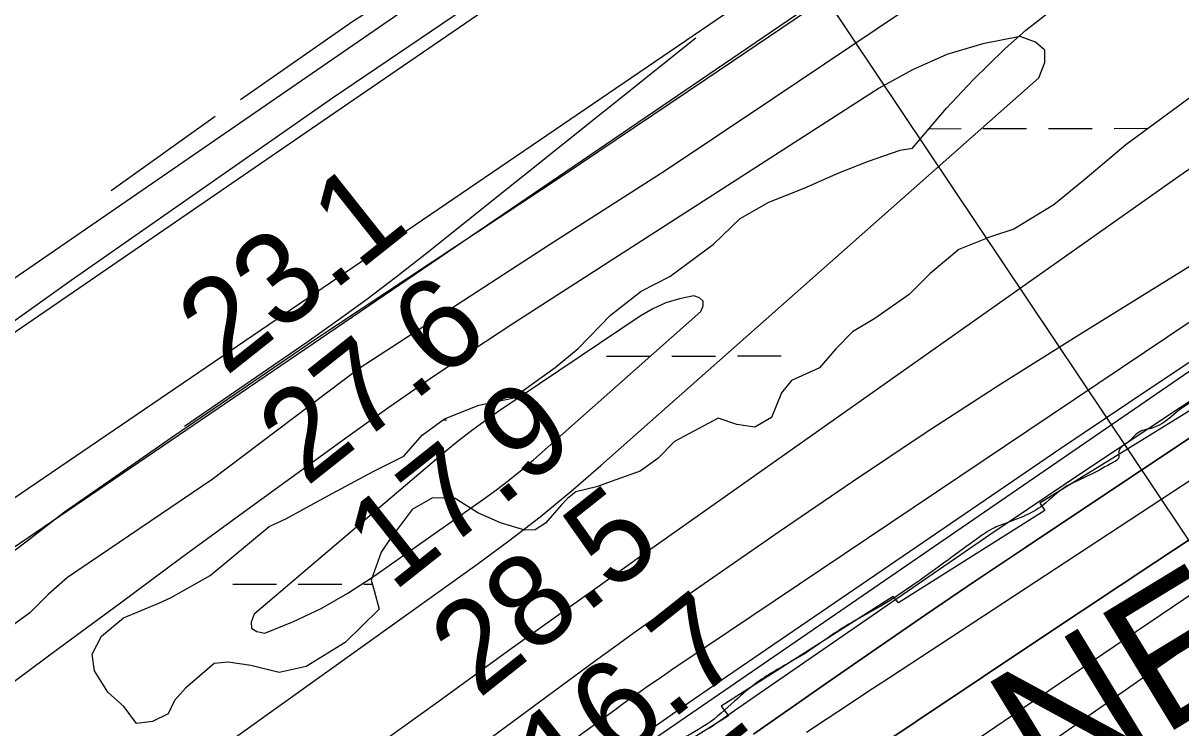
# Model space of a CAD drawing. Extents: x 3324104 to 3361979, y 612876 to 638273.
# Drawn here: x 3352974 to 3353821, y 621446 to 621962 of the extents above; entities that cross this region are included whole.
import ezdxf

# ---------------------------------------------------------------- set-up
doc = ezdxf.new("R2010")
doc.units = 0
for name, color, linetype in [('V-FLOD-BASE', 7, 'Continuous'), ('V-LEVE-TOET', 7, 'Continuous'), ('V-RIVR-EDGE', 7, 'Continuous'), ('V-RIVR-RANG', 7, 'Continuous'), ('V-ROAD-CNTR', 7, 'Continuous'), ('V-RRAP-FSHR', 7, 'Continuous'), ('V-RRAP-RVMT', 7, 'Continuous'), ('V-RRAP-RVMT-IDEN', 7, 'Continuous'), ('V-SURV-LINE', 7, 'Continuous'), ('V-TOPO-DPTH', 7, 'Continuous'), ('V-TOPO-MAJR', 7, 'Continuous'), ('V-TOPO-MINR', 7, 'Continuous'), ('V-TOPO-SHOR', 7, 'Continuous'), ('V-TOPO-WATR', 7, 'Continuous'), ('V-WETL-SWMP', 7, 'Continuous')]:
    doc.layers.add(name, color=color, linetype=linetype)

msp = doc.modelspace()

# ---------------------------------------------------------------- linework, layer by layer
at = {"layer": 'V-FLOD-BASE'}
msp.add_lwpolyline([(3352733.39, 621421.22), (3352808.07, 621469.05), (3352880.67, 621518.91), (3352907.8, 621537.87), (3352926.16, 621547.76), (3352952.63, 621565.33), (3352977.71, 621584.25), (3353004.14, 621604.57), (3353084.86, 621660.73), (3353186.64, 621730.26), (3353290.48, 621799.14), (3353369.22, 621851.16), (3353473.73, 621921.42), (3353593.83, 622002.91), (3353711.85, 622086.42), (3353832.66, 622166.54)], dxfattribs=at)
at = {"layer": 'V-LEVE-TOET'}
for points in [[(3352048.33, 621149.58), (3352281.39, 621294.26), (3352547.43, 621455.43), (3352729.05, 621574.03), (3352943.48, 621719.74), (3353193.4, 621891.29), (3353438.06, 622058.76), (3353677.49, 622220.84), (3353834.04, 622327.06), (3353864.34, 622344.83), (3353996.2, 622414.76), (3354263.85, 622558.67), (3354497.32, 622678.09), (3354750.45, 622815.11), (3355094.52, 623002.8), (3355436.28, 623169.16), (3355691.22, 623286.64)], [(3353844.21, 622130.37), (3353724.14, 622046.83), (3353616.99, 621970.35), (3353522.66, 621907.11), (3353443.93, 621854.41), (3353359.06, 621800.24), (3353219.89, 621709.53), (3353112.14, 621628.24), (3353006.28, 621556.59), (3352992.07, 621544.02)], [(3352992.07, 621544.02), (3352978.57, 621530.77), (3352962.29, 621518.84), (3352945.95, 621511.72), (3352931.66, 621504.64), (3352890.23, 621478.6), (3352825.74, 621436.41), (3352742.94, 621381.59), (3352604.42, 621293.63), (3352521.58, 621240.87), (3352486.39, 621210.81), (3352457.38, 621180.85), (3352433.13, 621153.03), (3352416.22, 621137.67), (3352403.32, 621129.92), (3352389.05, 621121.45), (3352371.31, 621115.69), (3352326.17, 621107.42), (3352304.33, 621100.21), (3352274.37, 621086.7), (3352237.68, 621064.85)]]:
    msp.add_lwpolyline(points, dxfattribs=at)
at = {"layer": 'V-RIVR-EDGE'}
msp.add_spline([(3356051.95, 622889.63), (3356029.15, 622881.43), (3356012.46, 622875.66), (3355994.6, 622867.17), (3355977.52, 622859.07), (3355958.5, 622850.97), (3355948.4, 622843.24), (3355934.03, 622834.75), (3355904.12, 622817.76), (3355878.1, 622802.31), (3355856.74, 622790.34), (3355829.95, 622776.44), (3355805.11, 622765.65), (3355764.72, 622744.81), (3355744.14, 622733.61), (3355694.06, 622710.85), (3355668.43, 622698.12), (3355641.64, 622685), (3355605.15, 622669.19), (3355569.44, 622657.26), (3355539.17, 622646.47), (3355510.83, 622636.85), (3355482.11, 622628.39), (3355461.93, 622623.01), (3355442.52, 622614.14), (3355422.73, 622607.21), (3355409.53, 622603.36), (3355388.97, 622597.59), (3355371.88, 622589.49), (3355348.98, 622581.02), (3355297.71, 622547.02), (3355260.04, 622525.78), (3355211.1, 622494.49), (3355190.13, 622484.46), (3355184.7, 622482.92), (3355179.26, 622477.89), (3355174.21, 622475.58), (3355160.62, 622470.96), (3355143.54, 622463.63), (3355133.06, 622457.07), (3355125.67, 622450.49), (3355113.25, 622443.93), (3355096.93, 622433.11), (3355081.02, 622426.95), (3355064.32, 622419.23), (3355056.95, 622418.86), (3355048.8, 622414.62), (3355041.8, 622406.88), (3355036.76, 622406.5), (3355031.32, 622405.74), (3355027.05, 622404.2), (3355017.34, 622396.08), (3355010.74, 622394.93), (3355001.42, 622388.36), (3354988.6, 622379.09), (3354972.29, 622369.43), (3354947.44, 622356.31), (3354937.73, 622351.68), (3354926.08, 622343.56), (3354903.15, 622326.56), (3354891.11, 622318.06), (3354883.33, 622307.22), (3354879.44, 622304.12), (3354875.17, 622302.58), (3354867.8, 622299.11), (3354853.03, 622288.29), (3354842.54, 622279.01), (3354826.61, 622267.41), (3354807.2, 622259.71), (3354793.23, 622255.47), (3354765.68, 622249.73), (3354748.61, 622245.5), (3354734.63, 622239.33), (3354712.11, 622227.37), (3354697.74, 622218.87), (3354685.31, 622209.98), (3354640.65, 622184.5), (3354622.01, 622176.01), (3354616.19, 622175.25), (3354603.38, 622167.52), (3354578.92, 622157.11), (3354554.46, 622147.48), (3354537.39, 622142.87), (3354530.78, 622137.84), (3354500.11, 622122.79), (3354463.61, 622102.33), (3354417.79, 622078.79), (3354386.33, 622060.64), (3354340.11, 622032.44), (3354321.08, 622021.25), (3354284.96, 621998.84), (3354257, 621982.24), (3354217, 621958.68), (3354194.08, 621942.84), (3354176.99, 621931.63), (3354157.57, 621921.98), (3354141.64, 621910.39), (3354135.42, 621904.2), (3354130.36, 621897.62), (3354120.65, 621891.05), (3354103.96, 621882.95), (3354075.58, 621856.65), (3354044.89, 621835.39), (3354013.04, 621812.21), (3353971.47, 621781.67), (3353947.77, 621763.5), (3353941.17, 621763.52), (3353935.35, 621762.76), (3353929.53, 621760.06), (3353924.87, 621756.58), (3353920.59, 621751.55), (3353917.08, 621742.64), (3353910.48, 621741.49), (3353904.66, 621738.4), (3353893.78, 621731.06), (3353879.8, 621721.4), (3353866.19, 621708.64), (3353854.92, 621697.42), (3353843.26, 621687.75), (3353839.77, 621688.54), (3353831.23, 621686.23), (3353823.08, 621681.21), (3353818.03, 621677.34), (3353800.94, 621666.14), (3353790.85, 621663.06), (3353781.91, 621654.94), (3353777.63, 621651.85), (3353776.07, 621648.75), (3353775.67, 621643.71), (3353772.18, 621641), (3353755.87, 621632.13), (3353735.68, 621622.09), (3353718.58, 621608.17), (3353704.21, 621600.45), (3353694.12, 621596.6), (3353683.64, 621592.36), (3353671.21, 621584.25), (3353642.07, 621562.99), (3353598.95, 621534.01), (3353578.37, 621522.43), (3353556.23, 621507.75), (3353547.68, 621501.95), (3353525.93, 621489.21), (3353513.12, 621481.09), (3353497.18, 621468.34), (3353476.98, 621450.94), (3353453.28, 621436.65), (3353435.8, 621424.67), (3353404.72, 621401.09), (3353378.3, 621380.21), (3353361.59, 621368.62), (3353339.46, 621355.1), (3353319.65, 621342.35), (3353299.45, 621329.99), (3353283.54, 621324.6), (3353273.05, 621317.65), (3353254.77, 621295.98), (3353236.88, 621275.47), (3353219.39, 621258.83), (3353195.69, 621241.44), (3353168.49, 621221.34), (3353137.81, 621201.64), (3353112.17, 621185.03), (3353065.55, 621151.79), (3353022.05, 621122.82), (3352993.29, 621100.39), (3352956, 621073.34), (3352907.05, 621037.78), (3352853.8, 620991.77), (3352787.76, 620942.29), (3352749.68, 620913.3), (3352736.85, 620900.92), (3352733.34, 620892.79), (3352728.67, 620886.59), (3352718.96, 620881.19), (3352691.78, 620864.58), (3352660.31, 620841.78), (3352640.5, 620828.25), (3352623.39, 620811.23), (3352605.12, 620792.27), (3352593.46, 620783), (3352582.59, 620778.76), (3352566.29, 620771.43), (3352548.04, 620764.49), (3352522.41, 620750.98), (3352494.45, 620735.54), (3352482.41, 620727.04), (3352479.3, 620723.17), (3352476.96, 620717.36), (3352470.74, 620711.94), (3352455.99, 620707.33), (3352443.18, 620700.38), (3352419.1, 620685.7), (3352392.3, 620669.09), (3352362.78, 620650.94), (3352339.08, 620634.32), (3352315.38, 620615.38), (3352284.68, 620590.63), (3352258.65, 620571.31), (3352228.74, 620550.05), (3352193.39, 620527.65), (3352156.88, 620504.86), (3352131.63, 620487.47), (3352093.95, 620462.36), (3352049.28, 620432.99), (3351990.23, 620391.26), (3351936.63, 620357.26), (3351851.55, 620293.87), (3351833.29, 620281.51), (3351816.98, 620273.79), (3351794.06, 620257.95), (3351767.65, 620240.95), (3351719.86, 620206.17), (3351680.63, 620177.57), (3351657.32, 620160.56), (3351637.11, 620145.87), (3351623.13, 620135.44), (3351603.32, 620124.24), (3351588.57, 620120.01), (3351567.22, 620109.59), (3351552.08, 620103.43), (3351538.1, 620096.48), (3351523.73, 620086.43), (3351510.91, 620076.38), (3351503.52, 620069.81), (3351495.35, 620057.42), (3351486, 620042.32), (3351479.39, 620032.64), (3351469.67, 620022.58), (3351448.3, 620006.34), (3351431.59, 619994.75), (3351404.78, 619973.88), (3351377.97, 619951.84), (3351358.93, 619936.37), (3351332.12, 619915.5), (3351306.08, 619892.29), (3351274.58, 619858.25), (3351238.83, 619826.92), (3351215.12, 619805.65), (3351171.59, 619767.75), (3351145.54, 619739.51), (3351124.55, 619722.11), (3351105.9, 619707.81), (3351089.59, 619696.99), (3351079.49, 619691.2), (3351074.04, 619683.45), (3351058.1, 619666.43), (3351043.34, 619655.22), (3351015.36, 619633.96), (3350999.05, 619623.14), (3350992.05, 619617.34), (3350979.23, 619606.13), (3350966.01, 619594.53), (3350951.25, 619582.15), (3350935.7, 619567.84), (3350923.26, 619555.08), (3350910.05, 619544.25), (3350888.29, 619528.02), (3350846.74, 619504.08), (3350821.49, 619490.18), (3350811.39, 619483.61), (3350805.96, 619480.52), (3350800.9, 619473.16), (3350797.41, 619473.17), (3350793.92, 619474.35), (3350788.88, 619473.58), (3350786.93, 619472.04), (3350785.37, 619467.39), (3350785.36, 619462.73), (3350779.53, 619456.15), (3350765.93, 619445.72), (3350746.11, 619428.7), (3350722.4, 619408.98), (3350716.19, 619407.06), (3350713.08, 619403.96), (3350711.13, 619396.99), (3350708.79, 619391.57), (3350704.52, 619391.58), (3350693.26, 619385.79), (3350686.65, 619379.6), (3350679.64, 619368.37), (3350661.38, 619354.45), (3350648.56, 619344.4), (3350645.46, 619344.8), (3350638.47, 619339.39), (3350623.32, 619330.5), (3350616.33, 619326.26), (3350602.35, 619317.37), (3350598.83, 619308.85), (3350582.91, 619299.19), (3350553.77, 619276), (3350526.18, 619255.51), (3350493.55, 619231.94), (3350474.9, 619219.57), (3350474.5, 619213.76), (3350470.22, 619207.17), (3350458.96, 619202.55), (3350446.14, 619194.05), (3350441.09, 619189.79), (3350438.76, 619186.31), (3350434.48, 619180.89), (3350414.67, 619167.76), (3350401.46, 619159.26), (3350384.75, 619146.89), (3350369.6, 619133.74), (3350356.39, 619125.24), (3350350.95, 619119.05), (3350347.43, 619109.36), (3350338.1, 619097.75), (3350324.88, 619083.82), (3350308.55, 619069.9), (3350300.39, 619062.56), (3350296.13, 619062.57), (3350291.47, 619062.19), (3350274.77, 619050.6), (3350258.45, 619037.45), (3350251.84, 619032.81), (3350244.08, 619029.34), (3350233.61, 619028.21), (3350227.39, 619024.34), (3350220.39, 619016.99), (3350213, 619007.32), (3350202.12, 618996.87), (3350193.57, 618989.52), (3350179.6, 618985.29), (3350173.77, 618980.65), (3350164.84, 618977.96), (3350162.12, 618975.25), (3350159.39, 618971.38), (3350154.33, 618963.64), (3350145.78, 618953.19), (3350125.96, 618938.11), (3350102.66, 618923.05), (3350094.5, 618918.41), (3350086.34, 618913), (3350075.07, 618901.01), (3350064.19, 618892.12), (3350039.32, 618873.57), (3350021.84, 618861.59), (3350002.03, 618848.84), (3349991.94, 618844.21), (3349964.36, 618826.44), (3349938.72, 618807.11), (3349915.41, 618792.82), (3349892.5, 618778.92), (3349868.02, 618761.91), (3349852.49, 618753.03), (3349842.79, 618749.95), (3349830.35, 618739.13), (3349804.32, 618720.19), (3349777.9, 618697.76), (3349751.86, 618677.66), (3349729.72, 618661.43), (3349703.69, 618642.88), (3349678.84, 618629.75), (3349648.93, 618611.99), (3349624.46, 618594.99), (3349592.61, 618575.67), (3349570.48, 618564.87), (3349549.5, 618548.63), (3349505.21, 618518.11), (3349479.19, 618499.94), (3349471.42, 618494.53), (3349458.99, 618487.59), (3349438.4, 618472.12), (3349412.37, 618452.41), (3349379.73, 618429.61), (3349350.21, 618410.29), (3349303.2, 618374.73), (3349277.56, 618357.73), (3349263.97, 618347.29), (3349241.43, 618330.68), (3349226.67, 618319.85), (3349207.25, 618306.33), (3349193.17, 618293.54)], degree=3, dxfattribs=at)
at = {"layer": 'V-RIVR-RANG'}
msp.add_line((3353550.98, 621996.45), (3354073.67, 621215.16), dxfattribs=at)
at = {"layer": 'V-ROAD-CNTR'}
msp.add_lwpolyline([(3353867.53, 622388.29), (3353812.96, 622356.52), (3353775.17, 622330.65), (3353711.04, 622287.55), (3353347.4, 622037.39), (3352894.69, 621725.66), (3352781.25, 621646.98), (3352684.03, 621579.35), (3352627.31, 621541.21), (3352581, 621513.51), (3352520.9, 621474.1), (3352415.36, 621410.23), (3351812.2, 621048.45), (3351739.17, 621002.97), (3351683.58, 620968.21)], dxfattribs=at)
at = {"layer": 'V-RRAP-FSHR'}
msp.add_lwpolyline([(3349156.55, 618293.48), (3349290.84, 618378.98), (3349409.37, 618477.79), (3349541.25, 618565.26), (3349771.64, 618715.9), (3349922.45, 618808.45), (3350215.79, 619019.76), (3350269.12, 619069.35), (3350501.35, 619248.31), (3350630.24, 619348.58), (3350981.59, 619636.83), (3351335.34, 619937.32), (3351550.69, 620108.65), (3351713.66, 620224.46), (3351812.36, 620304.63), (3352053.37, 620458.3), (3352414.71, 620728.03), (3352590.48, 620825.76), (3352682.34, 620894.14), (3352964.07, 621108.39), (3353211.76, 621284.79), (3354078.79, 621880.27)], dxfattribs=at)
at = {"layer": 'V-RRAP-RVMT'}
for p, q in [((3353833.32, 621682.07), (3353718.1, 621610.97)), ((3353718.1, 621610.97), (3353721.76, 621605.59)), ((3353721.76, 621605.59), (3353614.57, 621538.04)), ((3353610.69, 621542.69), (3353484.75, 621462.36)), ((3353614.57, 621538.04), (3353610.69, 621542.69)), ((3353484.75, 621462.36), (3353490.2, 621455.25)), ((3353490.2, 621455.25), (3353362.21, 621375.5))]:
    msp.add_line(p, q, dxfattribs=at)
at = {"layer": 'V-SURV-LINE'}
for points in [[(3352745.54, 621464.15), (3353945.71, 622281.36)], [(3353962.59, 622256.56), (3352762.42, 621439.34)]]:
    msp.add_lwpolyline(points, dxfattribs=at)
at = {"layer": 'V-TOPO-DPTH'}
for points in [[(3353508.48, 621441.86), (3353562.01, 621479.23), (3353598.23, 621504.35), (3353634.56, 621529.31), (3353671.04, 621554.03), (3353707.63, 621578.6), (3354161.88, 621881.5)], [(3353508.48, 621441.86), (3353562.01, 621479.23), (3353598.23, 621504.35), (3353634.56, 621529.31), (3353671.04, 621554.03), (3353707.63, 621578.6), (3354161.88, 621881.5)], [(3353868.06, 621740.85), (3353800.28, 621695.89), (3353732.83, 621650.44), (3353518.02, 621503.97), (3353489.5, 621484.39), (3353461.05, 621464.7), (3353432.72, 621444.85)], [(3354109.79, 621703.92), (3353576.52, 621331.22)], [(3354109.79, 621703.92), (3353576.52, 621331.22)], [(3353579.77, 621419.09), (3353724.04, 621515.5), (3353803.01, 621568.04), (3353882.11, 621620.39)], [(3353882.11, 621620.39), (3353803.01, 621568.04), (3353724.04, 621515.5), (3353579.77, 621419.09)]]:
    msp.add_lwpolyline(points, dxfattribs=at)
at = {"layer": 'V-TOPO-MAJR'}
for points in [[(3353077.77, 621402.88), (3353305.91, 621566.06), (3353329.3, 621583.35), (3353352.31, 621601.11), (3353374.77, 621619.59), (3353396.84, 621638.53), (3353717.48, 621922.52), (3353721.85, 621933.59), (3353721.76, 621942.64), (3353715, 621948.65), (3353703.79, 621952.64), (3353676.52, 621947.24), (3353650.09, 621939.54), (3353624.91, 621928.39), (3353600.58, 621914.95), (3353332.95, 621742.72), (3353302.21, 621722.57), (3353271.71, 621702.09), (3353241.55, 621681.09), (3353211.63, 621659.75), (3353180.48, 621637.14), (3353135.21, 621604.17), (3353090.02, 621571.1), (3353044.93, 621537.88), (3352999.91, 621504.57), (3352735.46, 621308.17)], [(3353091.79, 621667.31), (3353181.43, 621728.93), (3353203.53, 621744.48), (3353225.4, 621760.34), (3353246.92, 621776.68), (3353268.21, 621793.32), (3353466.35, 621951.78)], [(3353861.45, 621879.01), (3353819.82, 621850.09), (3353456.56, 621593.69), (3353425.13, 621571.44), (3353393.75, 621549.13), (3353362.44, 621526.72), (3353331.17, 621504.25), (3353316.06, 621493.35), (3353277.27, 621465.4), (3353238.46, 621437.46)]]:
    msp.add_lwpolyline(points, dxfattribs=at)
at = {"layer": 'V-TOPO-MINR'}
for points in [[(3354043.85, 621918.19), (3353744.67, 621732.73), (3353689.66, 621698.03), (3353635.02, 621662.76), (3353580.94, 621626.65), (3353527.23, 621589.97), (3353448.41, 621535.24), (3353434.43, 621525.45), (3353420.51, 621515.57), (3353406.67, 621505.58), (3353392.88, 621495.5), (3352987.58, 621196.59)], [(3353912.95, 621800.7), (3353456.83, 621494.35), (3353450.53, 621490.09), (3353444.24, 621485.81), (3353437.98, 621481.49), (3353431.73, 621477.16), (3353425.51, 621472.79), (3353419.29, 621468.4), (3353413.1, 621463.98), (3353406.93, 621459.54), (3352864.43, 621067.84)], [(3354206.15, 621799.15), (3353788.86, 621517.01), (3353748.88, 621489.94), (3353708.92, 621462.83), (3353669, 621435.67)], [(3353302.09, 621664.08), (3353292.46, 621656.52), (3353282.99, 621648.75), (3353142.81, 621529.7), (3353140.77, 621523.89), (3353141.04, 621519.43), (3353144.79, 621516.98), (3353150.84, 621515.88), (3353171.66, 621524.4), (3353191.93, 621533.97), (3353211.38, 621545.12), (3353230.28, 621557.33), (3353312.64, 621615.27), (3353321.61, 621621.81), (3353330.44, 621628.55), (3353339.03, 621635.58), (3353347.47, 621642.81), (3353469.94, 621751.28), (3353471.61, 621755.51), (3353471.58, 621758.96), (3353469, 621761.26), (3353464.71, 621762.79), (3353454.32, 621760.69), (3353444.27, 621757.69), (3353434.73, 621753.31), (3353425.54, 621748.02), (3353322.01, 621678.31), (3353311.97, 621671.3), (3353302.09, 621664.08)], [(3353868.06, 621740.85), (3353800.28, 621695.89), (3353732.83, 621650.44), (3353518.02, 621503.97), (3353489.5, 621484.39), (3353461.05, 621464.7), (3353432.72, 621444.85)], [(3353891.14, 621726.73), (3353821.21, 621681.04), (3353751.56, 621634.93), (3353682.34, 621588.2), (3353613.39, 621541.04), (3353512.97, 621471.69), (3353494.48, 621458.83), (3353476.05, 621445.9)], [(3353976.3, 621724.76), (3353607.3, 621482.6), (3353592.32, 621472.74), (3353577.34, 621462.88), (3353562.38, 621452.99), (3353547.43, 621443.08)], [(3354109.79, 621703.92), (3353576.52, 621331.22)], [(3353882.11, 621620.39), (3353803.01, 621568.04), (3353724.04, 621515.5), (3353579.77, 621419.09)]]:
    msp.add_lwpolyline(points, dxfattribs=at)
at = {"layer": 'V-TOPO-SHOR'}
msp.add_line((3353114.34, 621894.19), (3353038.28, 621839.61), dxfattribs=at)
for points in [[(3355651.33, 623306.1), (3355443.74, 623204.7), (3355259.41, 623107.78), (3355126.02, 623041.86), (3354985.99, 622962.8), (3354786.02, 622856.72), (3354599.02, 622754.96), (3354402.53, 622646.19), (3354239.91, 622564.02), (3354045.44, 622458.03), (3353808.21, 622323.23), (3353722.68, 622266.99), (3353654.19, 622217.88), (3353559.9, 622151.89), (3353401.12, 622043.72), (3353200.27, 621907.45), (3353008.97, 621774.07), (3352819.08, 621638.65), (3352713.88, 621569.06), (3352571.34, 621474.87), (3352516.97, 621443.14), (3352461.97, 621408.65), (3352340.37, 621334.68), (3352239.82, 621274.09)], [(3353261.08, 621992.88), (3353215.11, 621963.72), (3353132.86, 621906.27)]]:
    msp.add_lwpolyline(points, dxfattribs=at)
at = {"layer": 'V-TOPO-WATR'}
msp.add_lwpolyline([(3354161.88, 621881.5), (3353707.63, 621578.6), (3353671.04, 621554.03), (3353634.56, 621529.31), (3353598.23, 621504.35), (3353562.01, 621479.23), (3353508.48, 621441.86)], dxfattribs=at)
at = {"layer": 'V-WETL-SWMP'}
for p, q in [((3353636.99, 621885.18), (3353660.5, 621885.23)), ((3353676.5, 621885.25), (3353708.5, 621885.31)), ((3353724.5, 621885.34), (3353756.5, 621885.39)), ((3353772.5, 621885.42), (3353797.52, 621885.46)), ((3353400.79, 621718.6), (3353432.79, 621718.65)), ((3353448.79, 621718.68), (3353480.79, 621718.74)), ((3353496.79, 621718.77), (3353528.79, 621718.82)), ((3353281.27, 621671.96), (3353283.81, 621671.96)), ((3353127.17, 621551.62), (3353159.17, 621551.67)), ((3353175.17, 621551.7), (3353207.17, 621551.76)), ((3353223.17, 621551.79), (3353229.41, 621551.8))]:
    msp.add_line(p, q, dxfattribs=at)
for points in [[(3353403.85, 621748.72), (3353426.2, 621766.22), (3353447.3, 621776.85), (3353479.15, 621800.68), (3353498.74, 621819.51), (3353519.81, 621831.51), (3353545.72, 621841.53), (3353570.92, 621852.91), (3353592.73, 621861.48), (3353615.92, 621869.4), (3353624.82, 621870.91), (3353649.73, 621900.12), (3353669.29, 621921.01), (3353692.25, 621943.33), (3353707.8, 621957.29), (3353726.77, 621972), (3353753.32, 621984.77), (3353777.8, 621998.2), (3353808.56, 622004.86), (3353833.84, 622010.75)], [(3353840.15, 621916.88), (3353781.17, 621873.41), (3353751.39, 621848.24), (3353728.37, 621829.36), (3353699.16, 621811.74), (3353682.1, 621805.98), (3353658.93, 621796.69), (3353637.94, 621779.21), (3353622.41, 621763.87), (3353597.31, 621746.32), (3353581.01, 621736.46), (3353568.86, 621723.92), (3353556.74, 621710.01), (3353536.31, 621700.76), (3353528.91, 621691.73), (3353521.65, 621673.78), (3353509.42, 621666.72), (3353496.35, 621668.57), (3353482.56, 621673.16), (3353450.6, 621656.18), (3353438.45, 621643.64), (3353425.56, 621634.52), (3353407.83, 621628.06), (3353393.51, 621623.03), (3353378.48, 621619.36), (3353372.38, 621614.46)], [(3353372.38, 621614.46), (3353367.66, 621609.59), (3353356.21, 621596.37), (3353348.74, 621591.45), (3353341.2, 621591.33), (3353323.28, 621596.53), (3353306.71, 621603.81), (3353290.07, 621614.52), (3353273.6, 621614.94), (3353258.65, 621606.47), (3353242.53, 621584.95), (3353235.83, 621575.24), (3353228.61, 621554.55), (3353230.79, 621547.04), (3353234.44, 621533.38), (3353209.45, 621508.97), (3353180.92, 621491.37), (3353161.1, 621486.94), (3353140.44, 621492.09), (3353123.94, 621494.57), (3353113.67, 621493.72), (3353092.69, 621475.55), (3353084.6, 621466.51), (3353079.96, 621456.83), (3353068.39, 621451.16), (3353056.75, 621449.6), (3353047.64, 621461.8), (3353035.81, 621472.59), (3353025.96, 621488.2), (3353024.39, 621500.53), (3353031.04, 621513.67), (3353047.29, 621526.96), (3353073.18, 621537.66), (3353082.03, 621541.92), (3353110.58, 621558.15), (3353153.91, 621593.82), (3353166.16, 621599.51), (3353196.76, 621616.46), (3353230.08, 621634.14), (3353252.54, 621645.47), (3353266.01, 621660.78), (3353282.28, 621672.7), (3353307.5, 621682.7), (3353332.11, 621687.9), (3353363.31, 621710.35), (3353380.23, 621724.33), (3353403.85, 621748.72)]]:
    msp.add_lwpolyline(points, dxfattribs=at)

# ---------------------------------------------------------------- texts
at = {"layer": 'V-RIVR-RANG'}
for s, p in [('23.1', (3353121.97, 621703.29)), ('27.6', (3353181.01, 621622.47)), ('17.9', (3353244.59, 621545.27)), ('28.5', (3353307.14, 621467.24)), ('16.7', (3353369.48, 621389.05)), ('-5', (3353484.93, 621353))]:
    msp.add_text(s, height=67, rotation=38.42833, dxfattribs=at).set_placement(p)
at = {"layer": 'V-RRAP-RVMT-IDEN'}
msp.add_text('NEW', height=100, rotation=31.33691, dxfattribs=at).set_placement((3353724.7, 621389.08))

doc.saveas('drawing.dxf')
